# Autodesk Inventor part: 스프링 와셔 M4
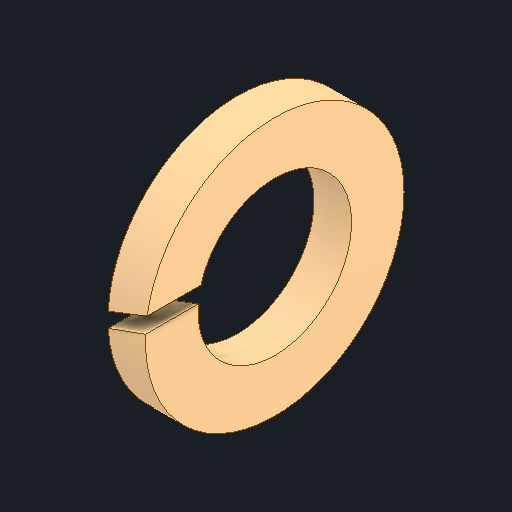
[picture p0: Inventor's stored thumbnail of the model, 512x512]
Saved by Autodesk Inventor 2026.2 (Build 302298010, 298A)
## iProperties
Created: 2026-03
Part Number: 스프링 와셔 M4
Material: 강철, 연강
Description: 스프링 잠금 와셔
Document SubType Name: Modeling
Designer: PC2-02
Density: 7.85 g/cm^3
Appearance: 기본값
Author: jhkim
Sending System: Autodesk Inventor 2026
Preprocessor: ST-DEVELOPER v20.1
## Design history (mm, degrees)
feature "Solid1"
node "솔리드1"
